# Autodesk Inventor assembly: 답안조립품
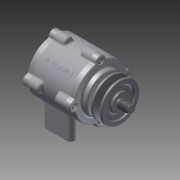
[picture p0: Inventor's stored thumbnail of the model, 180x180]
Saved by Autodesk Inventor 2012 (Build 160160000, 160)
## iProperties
Created: 2015-03
Part Number: 답안조립품
Document SubType Name: Assembly
Designer: Owner
Author: Owner
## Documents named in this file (10)
- C:\Documents and Settings\Owner\바탕 화면\450305V1001\답안조립품.iam
- C:\Documents and Settings\Owner\바탕 화면\450305V1001\본체.ipt
- C:\Documents and Settings\Owner\바탕 화면\450305V1001\베어링 6204.ipt
- C:\Documents and Settings\Owner\바탕 화면\450305V1001\커버.ipt
- C:\Documents and Settings\Owner\바탕 화면\450305V1001\커버2.ipt
- C:\Documents and Settings\Owner\바탕 화면\450305V1001\M 4 x 12.ipt
- C:\Documents and Settings\Owner\바탕 화면\450305V1001\축.ipt
- C:\Documents and Settings\Owner\바탕 화면\450305V1001\오일실.ipt
- C:\Documents and Settings\Owner\바탕 화면\450305V1001\키(4 x 4 x 12).ipt
- C:\Documents and Settings\Owner\바탕 화면\450305V1001\V벨트풀리.ipt
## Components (13 placed, 5 different names)
1. KS B 2023 6204 - 20 x 47 x 14:1
2. KS B 2023 6204 - 20 x 47 x 14:2
3. KS B 2804 D D - 20 32 8:1
4. KS B 1311 (I) 4 x 4 x 12:1 — 각도:1, 각도:2
5. 그루브 풀리1:1 — 각도:2
6. KS B 1003 - 미터 M 4 x 12:1
7. KS B 1003 - 미터 M 4 x 12:2
8. KS B 1003 - 미터 M 4 x 12:3
9. KS B 1003 - 미터 M 4 x 12:4
10. KS B 1003 - 미터 M 4 x 12:5
11. KS B 1003 - 미터 M 4 x 12:6
12. KS B 1003 - 미터 M 4 x 12:7
13. KS B 1003 - 미터 M 4 x 12:8
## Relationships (2: Angle 2)
- 각도:1 [Angle]: KS B 1311 (I) 4 x 4 x 12:1
- 각도:2 [Angle]: KS B 1311 (I) 4 x 4 x 12:1 ↔ 그루브 풀리1:1
